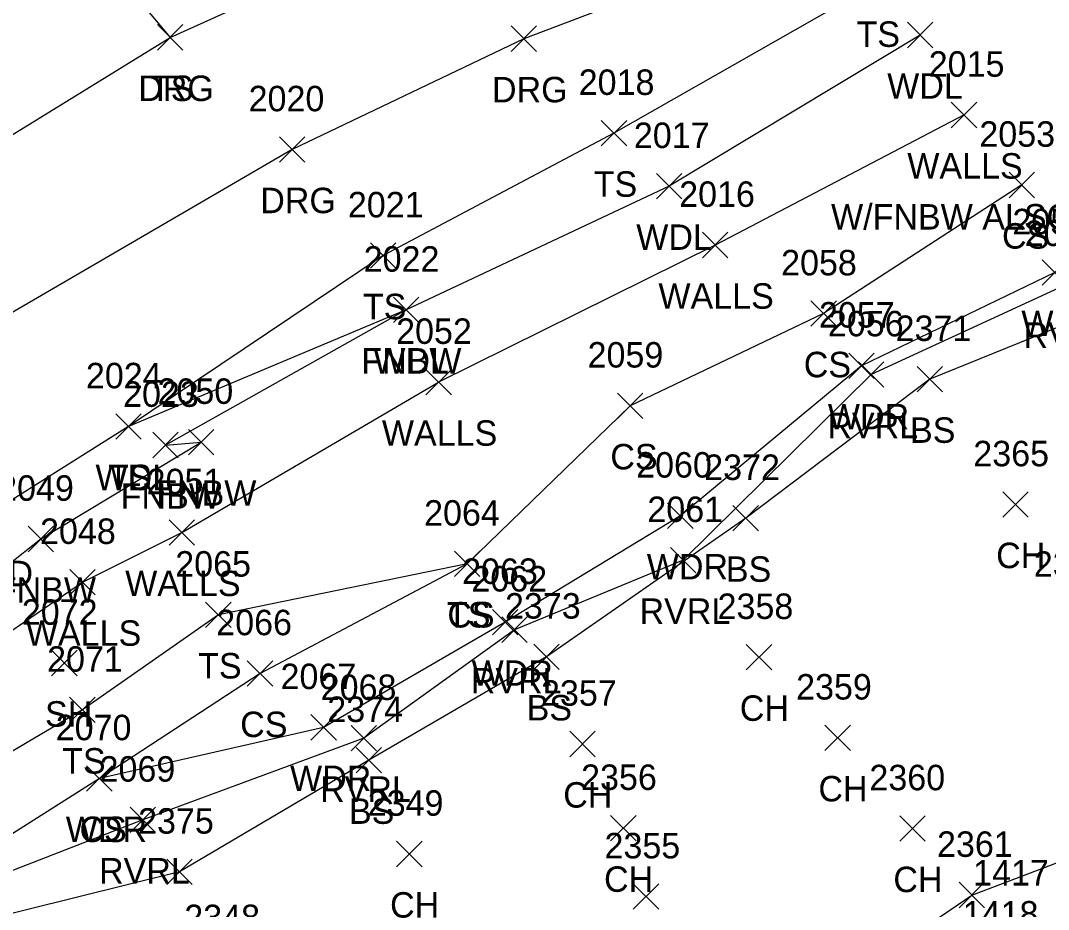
# Model space of a CAD drawing. Extents: x 1501299 to 1502485, y 381423 to 383765.
# Drawn here: x 1501669.5 to 1501750.2, y 383335.7 to 383405.5 of the extents above; entities that cross this region are included whole.
import ezdxf

# ---------------------------------------------------------------- set-up
doc = ezdxf.new("R2010")
doc.units = 0
for name, color, linetype in [('L_A', 7, 'Continuous'), ('L_C', 7, 'Continuous'), ('L_I', 7, 'Continuous'), ('L_TIC', 7, 'Continuous'), ('LAWA', 7, 'Continuous'), ('LAWE', 7, 'Continuous'), ('LELB', 7, 'Continuous'), ('LFNC', 7, 'Continuous'), ('LWS', 7, 'Continuous'), ('R_A', 7, 'Continuous'), ('R_I', 7, 'Continuous'), ('R_TIC', 7, 'Continuous'), ('RDG', 7, 'Continuous')]:
    doc.layers.add(name, color=color, linetype=linetype)

msp = doc.modelspace()

# ---------------------------------------------------------------- linework, layer by layer
at = {"layer": 'L_TIC'}
for points in [[(1501680.22, 383403.169), (1501682.22, 383405.169)], [(1501682.22, 383403.169), (1501680.22, 383405.169)], [(1501739.143, 383403.354), (1501741.143, 383405.354)], [(1501741.143, 383403.354), (1501739.143, 383405.354)], [(1501742.597, 383397.076), (1501744.597, 383399.076)], [(1501744.597, 383397.076), (1501742.597, 383399.076)], [(1501715.091, 383395.649), (1501717.091, 383397.649)], [(1501717.091, 383395.649), (1501715.091, 383397.649)], [(1501719.425, 383391.48), (1501721.425, 383393.48)], [(1501721.425, 383391.48), (1501719.425, 383393.48)], [(1501747.142, 383391.578), (1501749.142, 383393.578)], [(1501749.142, 383391.578), (1501747.142, 383393.578)], [(1501723.04, 383386.859), (1501725.04, 383388.859)], [(1501725.04, 383386.859), (1501723.04, 383388.859)], [(1501696.952, 383386.033), (1501698.952, 383388.033)], [(1501698.952, 383386.033), (1501696.952, 383388.033)], [(1501749.74, 383384.706), (1501751.74, 383386.706)], [(1501751.74, 383384.706), (1501749.74, 383386.706)], [(1501698.763, 383381.767), (1501700.763, 383383.767)], [(1501700.763, 383381.767), (1501698.763, 383383.767)], [(1501698.763, 383381.767), (1501700.763, 383383.767)], [(1501700.763, 383381.767), (1501698.763, 383383.767)], [(1501731.564, 383381.477), (1501733.564, 383383.477)], [(1501733.564, 383381.477), (1501731.564, 383383.477)], [(1501734.534, 383377.38), (1501736.534, 383379.38)], [(1501736.534, 383377.38), (1501734.534, 383379.38)], [(1501735.295, 383376.69), (1501737.295, 383378.69)], [(1501737.295, 383376.69), (1501735.295, 383378.69)], [(1501701.312, 383376.097), (1501703.312, 383378.097)], [(1501703.312, 383376.097), (1501701.312, 383378.097)], [(1501701.312, 383376.097), (1501703.312, 383378.097)], [(1501703.312, 383376.097), (1501701.312, 383378.097)], [(1501739.914, 383376.326), (1501741.914, 383378.326)], [(1501741.914, 383376.326), (1501739.914, 383378.326)], [(1501716.363, 383374.239), (1501718.363, 383376.239)], [(1501718.363, 383374.239), (1501716.363, 383376.239)], [(1501676.935, 383372.609), (1501678.935, 383374.609)], [(1501678.935, 383372.609), (1501676.935, 383374.609)], [(1501676.935, 383372.609), (1501678.935, 383374.609)], [(1501678.935, 383372.609), (1501676.935, 383374.609)], [(1501679.858, 383371.153), (1501681.858, 383373.153)], [(1501681.858, 383371.153), (1501679.858, 383373.153)], [(1501682.649, 383371.385), (1501684.649, 383373.385)], [(1501684.649, 383371.385), (1501682.649, 383373.385)], [(1501682.649, 383371.385), (1501684.649, 383373.385)], [(1501684.649, 383371.385), (1501682.649, 383373.385)], [(1501746.635, 383366.485), (1501748.635, 383368.485)], [(1501748.635, 383366.485), (1501746.635, 383368.485)], [(1501720.306, 383365.598), (1501722.306, 383367.598)], [(1501722.306, 383365.598), (1501720.306, 383367.598)], [(1501725.442, 383365.412), (1501727.442, 383367.412)], [(1501727.442, 383365.412), (1501725.442, 383367.412)], [(1501681.14, 383364.291), (1501683.14, 383366.291)], [(1501683.14, 383364.291), (1501681.14, 383366.291)], [(1501670.047, 383363.777), (1501672.047, 383365.777)], [(1501672.047, 383363.777), (1501670.047, 383365.777)], [(1501703.558, 383361.823), (1501705.558, 383363.823)], [(1501705.558, 383361.823), (1501703.558, 383363.823)], [(1501703.558, 383361.823), (1501705.558, 383363.823)], [(1501705.558, 383361.823), (1501703.558, 383363.823)], [(1501720.533, 383362.11), (1501722.533, 383364.11)], [(1501722.533, 383362.11), (1501720.533, 383364.11)], [(1501673.332, 383360.387), (1501675.332, 383362.387)], [(1501675.332, 383360.387), (1501673.332, 383362.387)], [(1501684.003, 383357.821), (1501686.003, 383359.821)], [(1501686.003, 383357.821), (1501684.003, 383359.821)], [(1501706.543, 383357.247), (1501708.543, 383359.247)], [(1501708.543, 383357.247), (1501706.543, 383359.247)], [(1501707.276, 383356.65), (1501709.276, 383358.65)], [(1501709.276, 383356.65), (1501707.276, 383358.65)], [(1501671.899, 383354.038), (1501673.899, 383356.038)], [(1501673.899, 383354.038), (1501671.899, 383356.038)], [(1501709.788, 383354.524), (1501711.788, 383356.524)], [(1501711.788, 383354.524), (1501709.788, 383356.524)], [(1501726.491, 383354.494), (1501728.491, 383356.494)], [(1501728.491, 383354.494), (1501726.491, 383356.494)], [(1501687.28, 383353.218), (1501689.28, 383355.218)], [(1501689.28, 383353.218), (1501687.28, 383355.218)], [(1501673.317, 383350.353), (1501675.317, 383352.353)], [(1501675.317, 383350.353), (1501673.317, 383352.353)], [(1501692.275, 383348.984), (1501694.275, 383350.984)], [(1501694.275, 383348.984), (1501692.275, 383350.984)], [(1501695.432, 383348.133), (1501697.432, 383350.133)], [(1501697.432, 383348.133), (1501695.432, 383350.133)], [(1501732.67, 383348.167), (1501734.67, 383350.167)], [(1501734.67, 383348.167), (1501732.67, 383350.167)], [(1501712.617, 383347.679), (1501714.617, 383349.679)], [(1501714.617, 383347.679), (1501712.617, 383349.679)], [(1501695.826, 383346.405), (1501697.826, 383348.405)], [(1501697.826, 383346.405), (1501695.826, 383348.405)], [(1501674.651, 383344.973), (1501676.651, 383346.973)], [(1501676.651, 383344.973), (1501674.651, 383346.973)], [(1501674.651, 383344.973), (1501676.651, 383346.973)], [(1501676.651, 383344.973), (1501674.651, 383346.973)], [(1501678.062, 383341.719), (1501680.062, 383343.719)], [(1501680.062, 383341.719), (1501678.062, 383343.719)], [(1501715.823, 383341.066), (1501717.823, 383343.066)], [(1501717.823, 383341.066), (1501715.823, 383343.066)], [(1501738.556, 383341.042), (1501740.556, 383343.042)], [(1501740.556, 383341.042), (1501738.556, 383343.042)], [(1501699.01, 383339.04), (1501701.01, 383341.04)], [(1501701.01, 383339.04), (1501699.01, 383341.04)], [(1501680.956, 383337.634), (1501682.956, 383339.634)], [(1501682.956, 383337.634), (1501680.956, 383339.634)], [(1501717.607, 383335.694), (1501719.607, 383337.694)], [(1501719.607, 383335.694), (1501717.607, 383337.694)], [(1501743.215, 383335.813), (1501745.215, 383337.813)], [(1501745.215, 383335.813), (1501743.215, 383337.813)]]:
    msp.add_lwpolyline(points, dxfattribs=at)
at = {"layer": 'LAWA'}
for points in [[(1501740.143, 383404.354), (1501720.425, 383392.48), (1501699.763, 383382.767), (1501677.935, 383373.609), (1501665.955, 383366.069), (1501653.629, 383358.895), (1501638.285, 383346.961), (1501632.179, 383342.995), (1501621.074, 383344.333), (1501627.11, 383337.683), (1501637.668, 383334.383)], [(1501750.74, 383385.706), (1501735.534, 383378.38), (1501721.306, 383366.598), (1501707.543, 383358.247), (1501693.275, 383349.984), (1501675.651, 383345.973), (1501663.959, 383338.57), (1501648.341, 383333.739), (1501637.668, 383334.383)]]:
    msp.add_lwpolyline(points, dxfattribs=at)
at = {"layer": 'LAWE'}
msp.add_lwpolyline([(1501751.7, 383384.782), (1501736.295, 383377.69), (1501721.533, 383363.11), (1501708.276, 383357.65), (1501696.432, 383349.133), (1501679.062, 383342.719), (1501664.765, 383337.172), (1501649.638, 383330.877), (1501644.08, 383325.549), (1501629.198, 383322.948), (1501623.396, 383326.029)], dxfattribs=at)
at = {"layer": 'LELB'}
for points in [[(1501689.495, 383469.9), (1501677.3, 383444.427), (1501658.239, 383430.369), (1501672.608, 383414.438), (1501681.22, 383404.169)], [(1501736.74, 383408.422), (1501716.091, 383396.649), (1501697.952, 383387.033), (1501677.935, 383373.609)], [(1501748.142, 383392.578), (1501732.564, 383382.477), (1501717.363, 383375.239), (1501704.558, 383362.823), (1501688.28, 383354.218), (1501675.651, 383345.973)], [(1501755, 383383.033), (1501740.914, 383377.326), (1501726.442, 383366.412), (1501710.788, 383355.524), (1501696.826, 383347.405), (1501681.956, 383338.634), (1501665.785, 383334.622), (1501652.745, 383328.441), (1501646.391, 383322.759), (1501637.585, 383320.905), (1501629.255, 383319.743), (1501624.747, 383320.366)], [(1501704.558, 383362.823), (1501685.003, 383358.821), (1501674.317, 383351.353), (1501662.456, 383344.366), (1501648.341, 383333.739), (1501644.08, 383325.549)], [(1501590.761, 383266.457), (1501598.871, 383270.571), (1501605.035, 383275.317), (1501612.707, 383279.234), (1501613.789, 383281.85), (1501615.914, 383283.693), (1501614.455, 383284.683), (1501622.35, 383292.222), (1501627.416, 383296.435), (1501634.13, 383302.054), (1501643.772, 383300.983), (1501650.033, 383300.072), (1501651.493, 383297.792), (1501662.757, 383297.227), (1501671.557, 383298.422), (1501684.76, 383303.845), (1501698.893, 383313.194), (1501704.538, 383312.156), (1501711.847, 383316.203), (1501724.827, 383323.61), (1501744.215, 383336.813), (1501764.443, 383344.5)]]:
    msp.add_lwpolyline(points, dxfattribs=at)
at = {"layer": 'LFNC'}
for points in [[(1501699.763, 383382.767), (1501680.858, 383372.153), (1501683.649, 383372.385)], [(1501633.369, 383341.084), (1501639.45, 383343.232), (1501655.168, 383352.235), (1501671.047, 383364.777), (1501683.649, 383372.385)]]:
    msp.add_lwpolyline(points, dxfattribs=at)
at = {"layer": 'LWS'}
for points in [[(1501743.597, 383398.076), (1501724.04, 383387.859), (1501702.312, 383377.097)], [(1501642.667, 383338.571), (1501657.478, 383349.901), (1501674.332, 383361.387), (1501682.14, 383365.291), (1501702.312, 383377.097)]]:
    msp.add_lwpolyline(points, dxfattribs=at)
at = {"layer": 'R_TIC'}
for points in [[(1501680.22, 383403.169), (1501682.22, 383405.169)], [(1501682.22, 383403.169), (1501680.22, 383405.169)], [(1501708.016, 383403.067), (1501710.016, 383405.067)], [(1501710.016, 383403.067), (1501708.016, 383405.067)], [(1501689.807, 383394.363), (1501691.807, 383396.363)], [(1501691.807, 383394.363), (1501689.807, 383396.363)]]:
    msp.add_lwpolyline(points, dxfattribs=at)
at = {"layer": 'RDG'}
for points in [[(1501585.888, 383364.546), (1501592.449, 383361.853), (1501598.939, 383359.572), (1501609.156, 383359.828), (1501620.557, 383365.386), (1501633.637, 383372.08), (1501645.617, 383382.098), (1501657.095, 383388.246), (1501660.515, 383391.446), (1501681.22, 383404.169), (1501705.776, 383415.265), (1501726.712, 383424.327)], [(1501733.479, 383413.356), (1501709.016, 383404.067), (1501690.807, 383395.363), (1501661.87, 383378.539), (1501644.375, 383366.495), (1501625.853, 383354.693), (1501614.404, 383347.477), (1501609.625, 383341.209), (1501607.043, 383333.417)]]:
    msp.add_lwpolyline(points, dxfattribs=at)

# ---------------------------------------------------------------- texts
at = {"layer": 'L_A'}
for s, p in [('TS', (1501735.149, 383403.422)), ('TS', (1501679.629, 383399.169)), ('WDL', (1501737.56, 383399.354)), ('WALLS', (1501739.141, 383393.076)), ('TS', (1501714.501, 383391.649)), ('WDL', (1501717.842, 383387.48)), ('CS', (1501746.583, 383387.578)), ('WALLS', (1501719.584, 383382.859)), ('TS', (1501696.362, 383382.033)), ('WDR', (1501748.103, 383380.706)), ('RVRL', (1501748.267, 383379.782)), ('FNBW', (1501696.235, 383377.767)), ('WDL', (1501697.18, 383377.767)), ('CS', (1501731.005, 383377.477)), ('WDR', (1501732.896, 383373.38)), ('RVRL', (1501732.862, 383372.69)), ('BS', (1501739.355, 383372.326)), ('WALLS', (1501697.855, 383372.097)), ('WALLS', (1501697.855, 383372.097)), ('CS', (1501715.804, 383370.239)), ('WDL', (1501675.352, 383368.609)), ('TS', (1501676.344, 383368.609)), ('FNBW', (1501677.33, 383367.153)), ('FNBW', (1501680.121, 383367.385)), ('FNBW', (1501680.121, 383367.385)), ('CH', (1501746.123, 383362.485)), ('FNWD', (1501662.42, 383361.069)), ('WDR', (1501718.669, 383361.598)), ('BS', (1501724.883, 383361.412)), ('WALLS', (1501677.683, 383360.291)), ('FNBW', (1501667.519, 383359.777)), ('TS', (1501702.967, 383357.823)), ('CS', (1501702.999, 383357.823)), ('RVRL', (1501718.1, 383358.11)), ('WALLS', (1501669.876, 383356.387)), ('TS', (1501683.413, 383353.821)), ('WDR', (1501704.905, 383353.247)), ('RVRL', (1501704.843, 383352.65)), ('BS', (1501709.229, 383350.524)), ('CH', (1501725.98, 383350.494)), ('SH', (1501671.387, 383350.038)), ('CS', (1501686.721, 383349.218)), ('TS', (1501672.727, 383346.353)), ('WDR', (1501690.637, 383344.984)), ('RVRL', (1501692.999, 383344.133)), ('CH', (1501732.158, 383344.167)), ('CH', (1501712.105, 383343.679)), ('BS', (1501695.267, 383342.405)), ('WDR', (1501673.013, 383340.973)), ('CS', (1501674.092, 383340.973)), ('RVRL', (1501675.629, 383337.719)), ('CH', (1501715.311, 383337.066)), ('CH', (1501738.044, 383337.042)), ('CH', (1501698.498, 383335.04))]:
    msp.add_text(s, height=2, dxfattribs=at).set_placement(p)
at = {"layer": 'L_C'}
msp.add_text('W/FNBW ALSO', height=2, dxfattribs=at).set_placement((1501733.149, 383389.076))
at = {"layer": 'L_I'}
for s, p in [('2015', (1501740.826, 383401.076)), ('2018', (1501713.32, 383399.649)), ('2017', (1501717.653, 383395.48)), ('2053', (1501744.803, 383395.578)), ('2016', (1501721.214, 383390.859)), ('2021', (1501695.181, 383390.033)), ('2054', (1501747.402, 383388.706)), ('2055', (1501748.362, 383387.782)), ('2022', (1501696.424, 383385.767)), ('2022', (1501696.424, 383385.767)), ('2058', (1501729.225, 383385.477)), ('2057', (1501732.195, 383381.38)), ('2056', (1501732.902, 383380.69)), ('2052', (1501698.973, 383380.097)), ('2052', (1501698.973, 383380.097)), ('2371', (1501738.221, 383380.326)), ('2059', (1501714.017, 383378.239)), ('2024', (1501674.596, 383376.609)), ('2024', (1501674.596, 383376.609)), ('2023', (1501677.519, 383375.153)), ('2050', (1501680.223, 383375.385)), ('2050', (1501680.223, 383375.385)), ('2365', (1501744.328, 383370.485)), ('2060', (1501717.834, 383369.598)), ('2372', (1501723.182, 383369.412)), ('2051', (1501679.368, 383368.291)), ('2049', (1501667.7, 383367.777)), ('2061', (1501718.714, 383366.11)), ('2064', (1501701.172, 383365.823)), ('2064', (1501701.172, 383365.823)), ('2048', (1501670.994, 383364.387)), ('2065', (1501681.617, 383361.821)), ('2364', (1501749.084, 383361.811)), ('2063', (1501704.157, 383361.247)), ('2062', (1501704.891, 383360.65)), ('2072', (1501669.561, 383358.038)), ('2373', (1501707.529, 383358.524)), ('2358', (1501724.232, 383358.494)), ('2066', (1501684.839, 383357.218)), ('2071', (1501671.546, 383354.353)), ('2067', (1501689.889, 383352.984)), ('2068', (1501693.046, 383352.133)), ('2359', (1501730.403, 383352.167)), ('2357', (1501710.357, 383351.679)), ('2374', (1501693.566, 383350.405)), ('2070', (1501672.225, 383348.973)), ('2070', (1501672.225, 383348.973)), ('2069', (1501675.669, 383345.719)), ('2356', (1501713.508, 383345.066)), ('2360', (1501736.162, 383345.042)), ('2349', (1501696.742, 383343.04)), ('2375', (1501678.696, 383341.634)), ('2355', (1501715.348, 383339.694)), ('2361', (1501741.475, 383339.813)), ('1417', (1501744.315, 383337.561)), ('1418', (1501743.497, 383334.34)), ('2348', (1501682.328, 383334.059))]:
    msp.add_text(s, height=2, dxfattribs=at).set_placement(p)
at = {"layer": 'R_A'}
for p in [(1501678.708, 383399.169), (1501706.505, 383399.067), (1501688.295, 383390.363)]:
    msp.add_text('DRG', height=2, dxfattribs=at).set_placement(p)
at = {"layer": 'R_I'}
msp.add_text('2020', height=2, dxfattribs=at).set_placement((1501687.382, 383398.363))

doc.saveas('drawing.dxf')
